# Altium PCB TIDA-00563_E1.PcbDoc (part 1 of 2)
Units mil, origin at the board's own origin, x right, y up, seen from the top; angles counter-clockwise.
Board outline 2300 x 2550 mil, 4 copper layers (Top Layer, MidLayer1 (GND), MidLayer2 (PWR), Bottom Layer), stack 79.8 mil thick; 81 components, 52 nets, 279 pads, 126 vias.
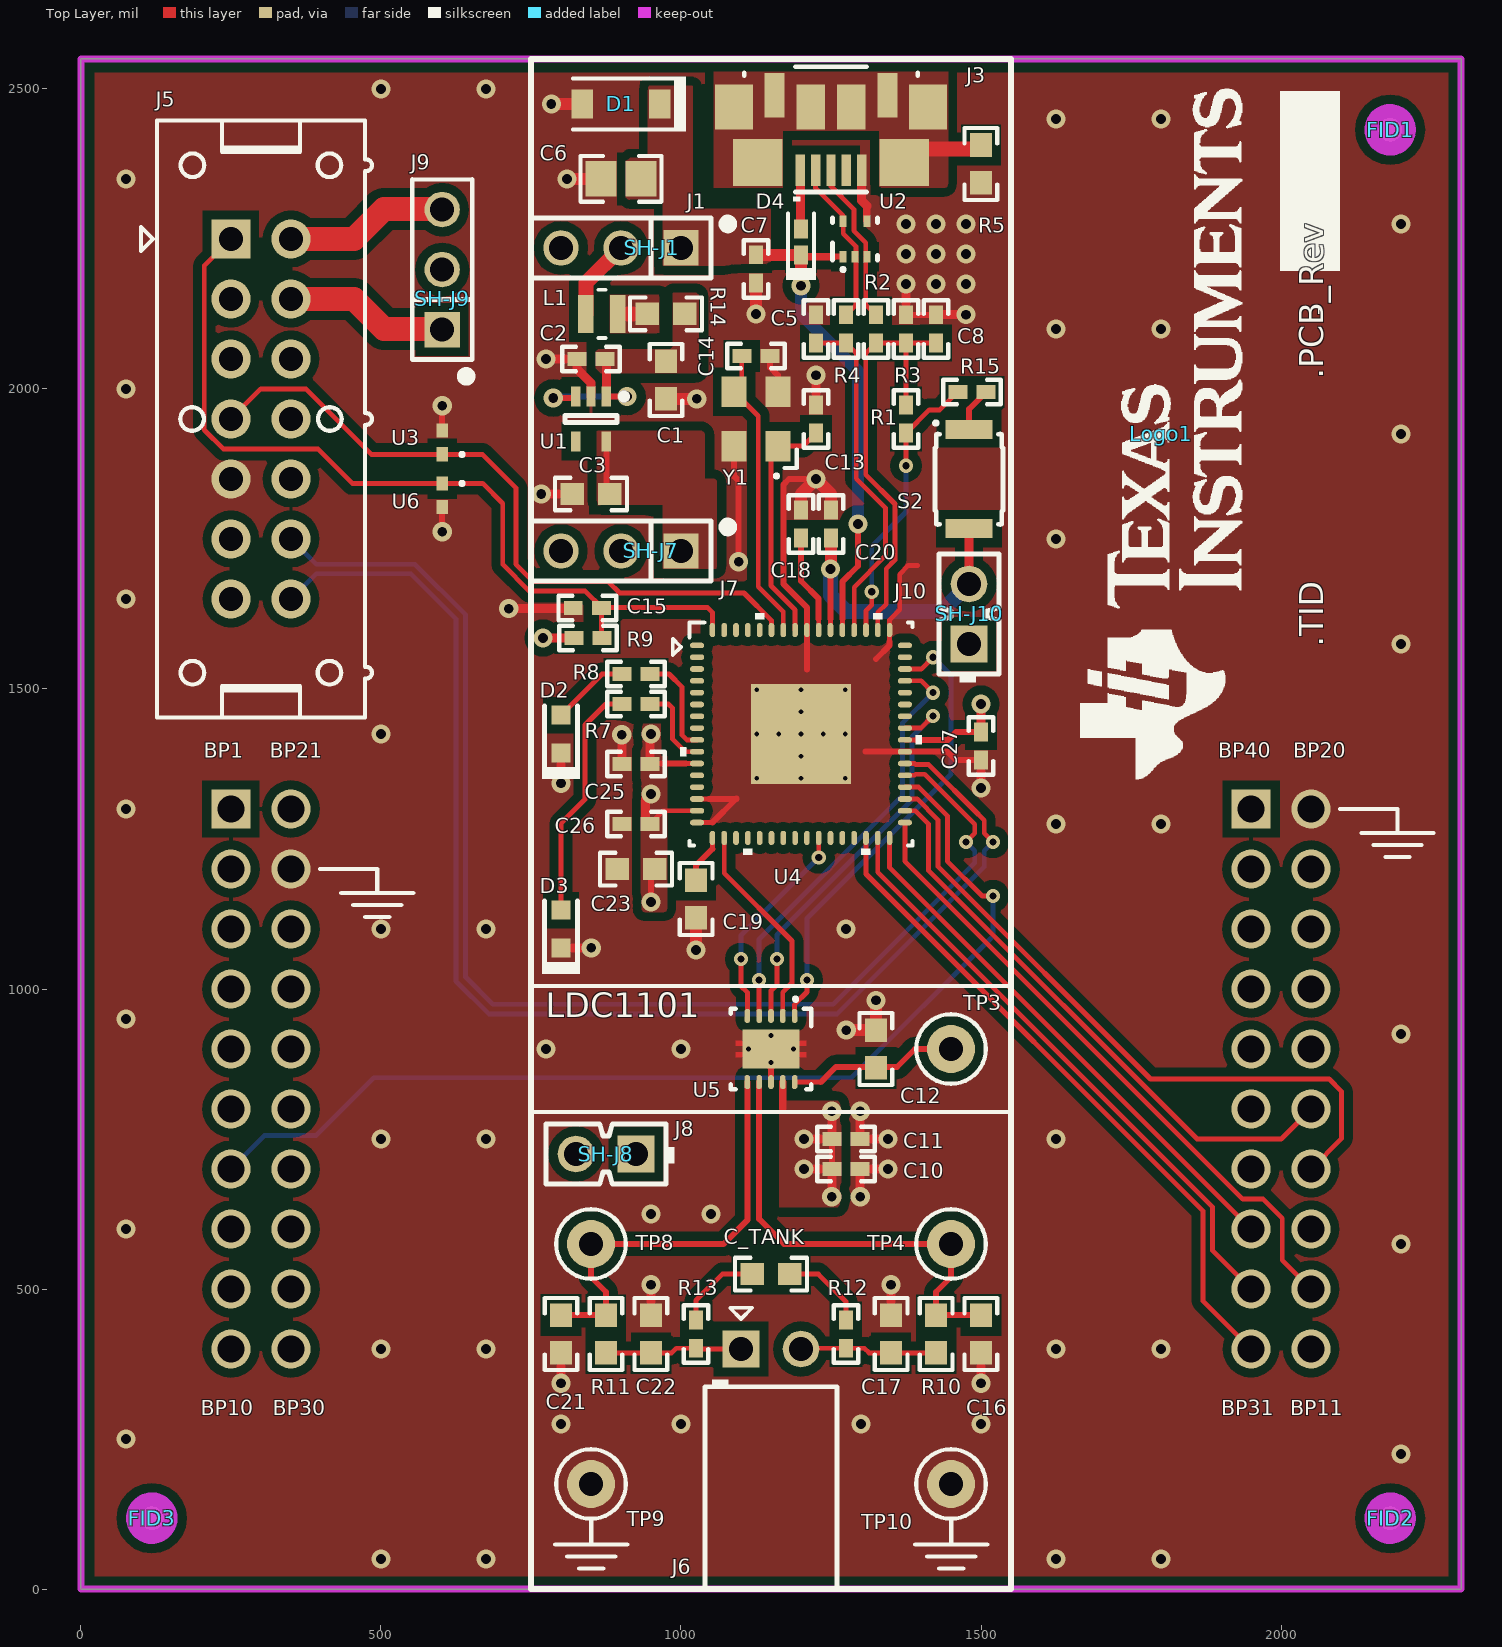
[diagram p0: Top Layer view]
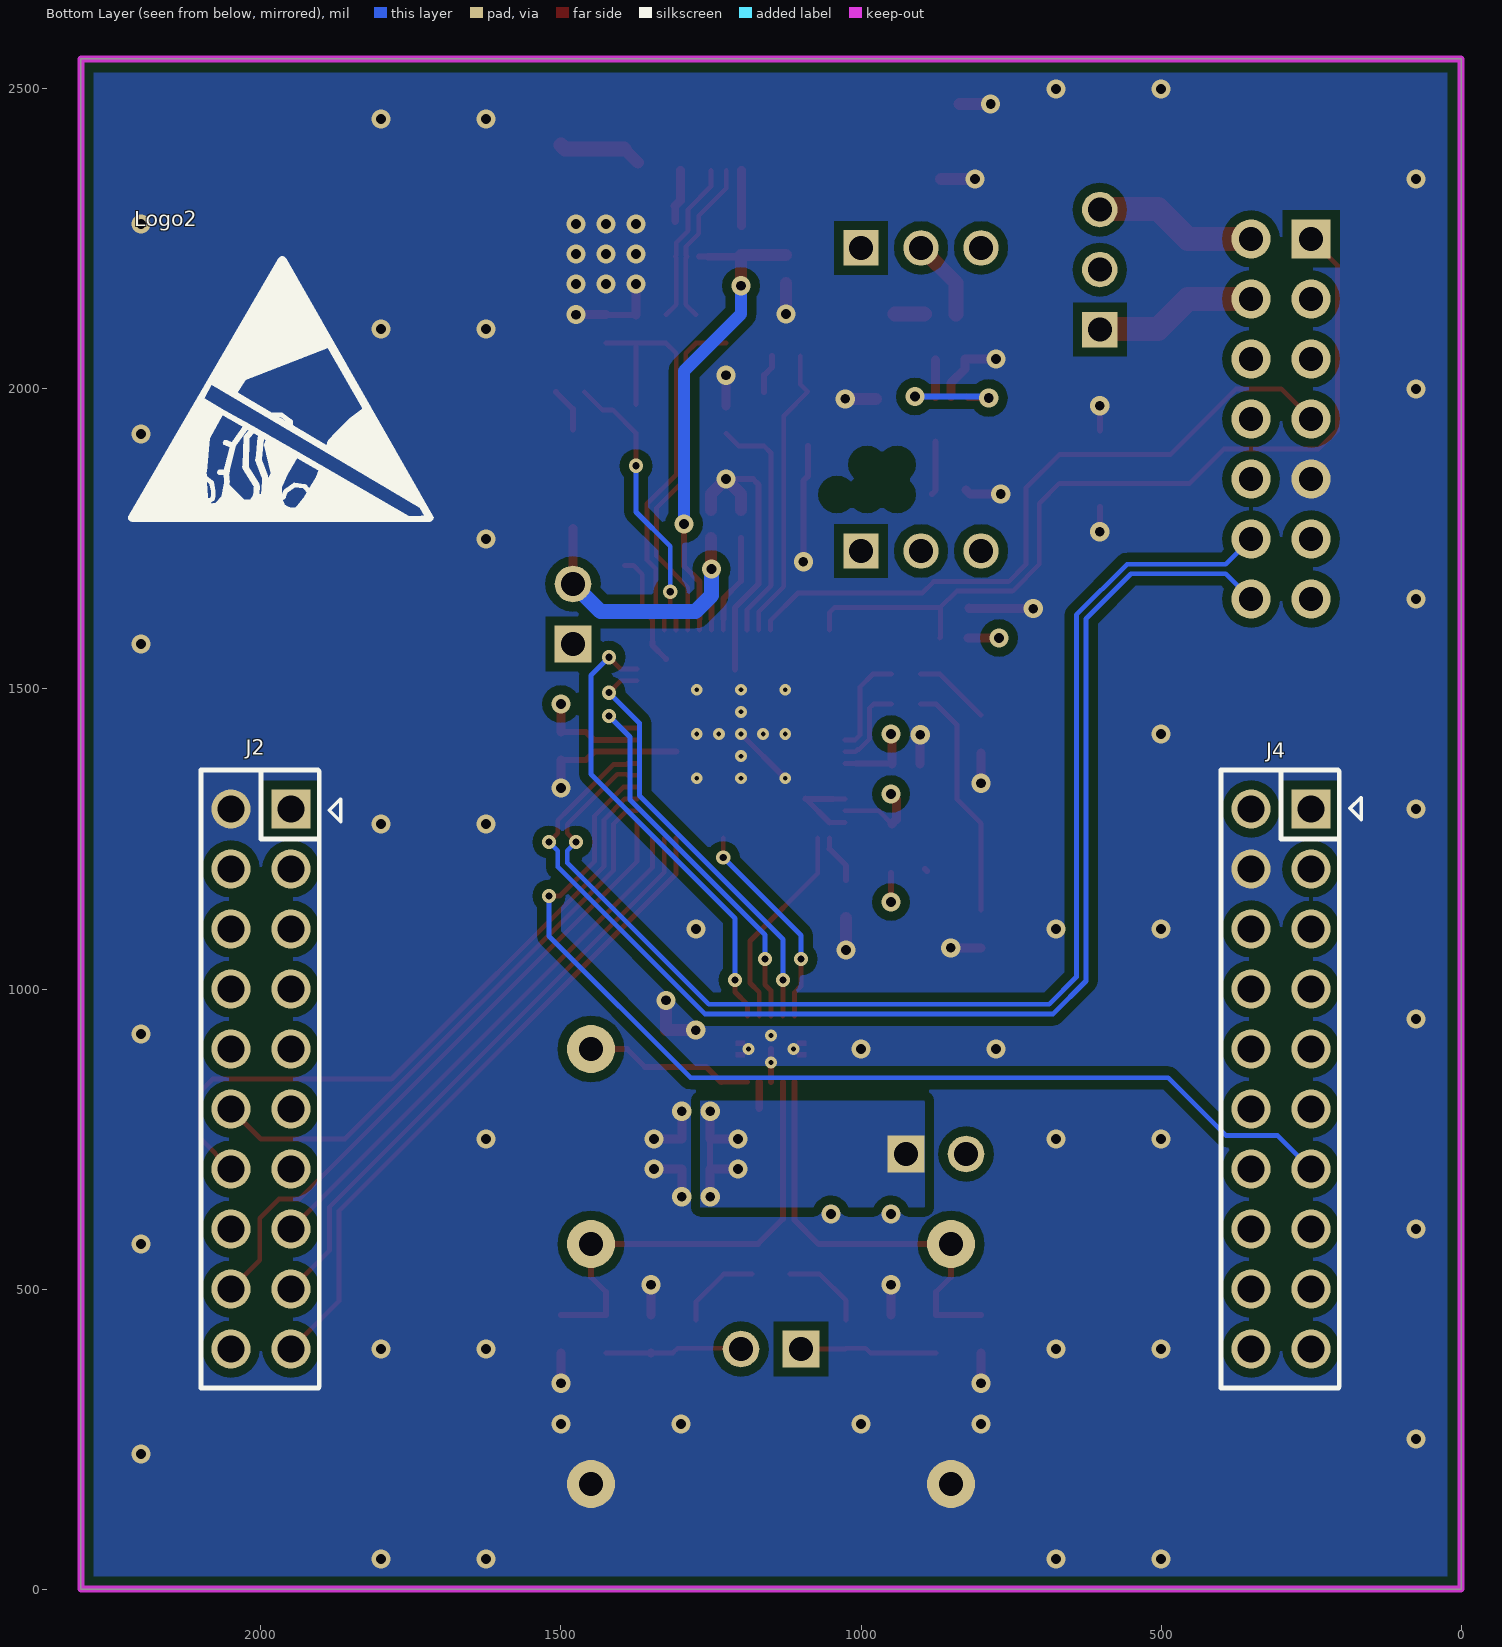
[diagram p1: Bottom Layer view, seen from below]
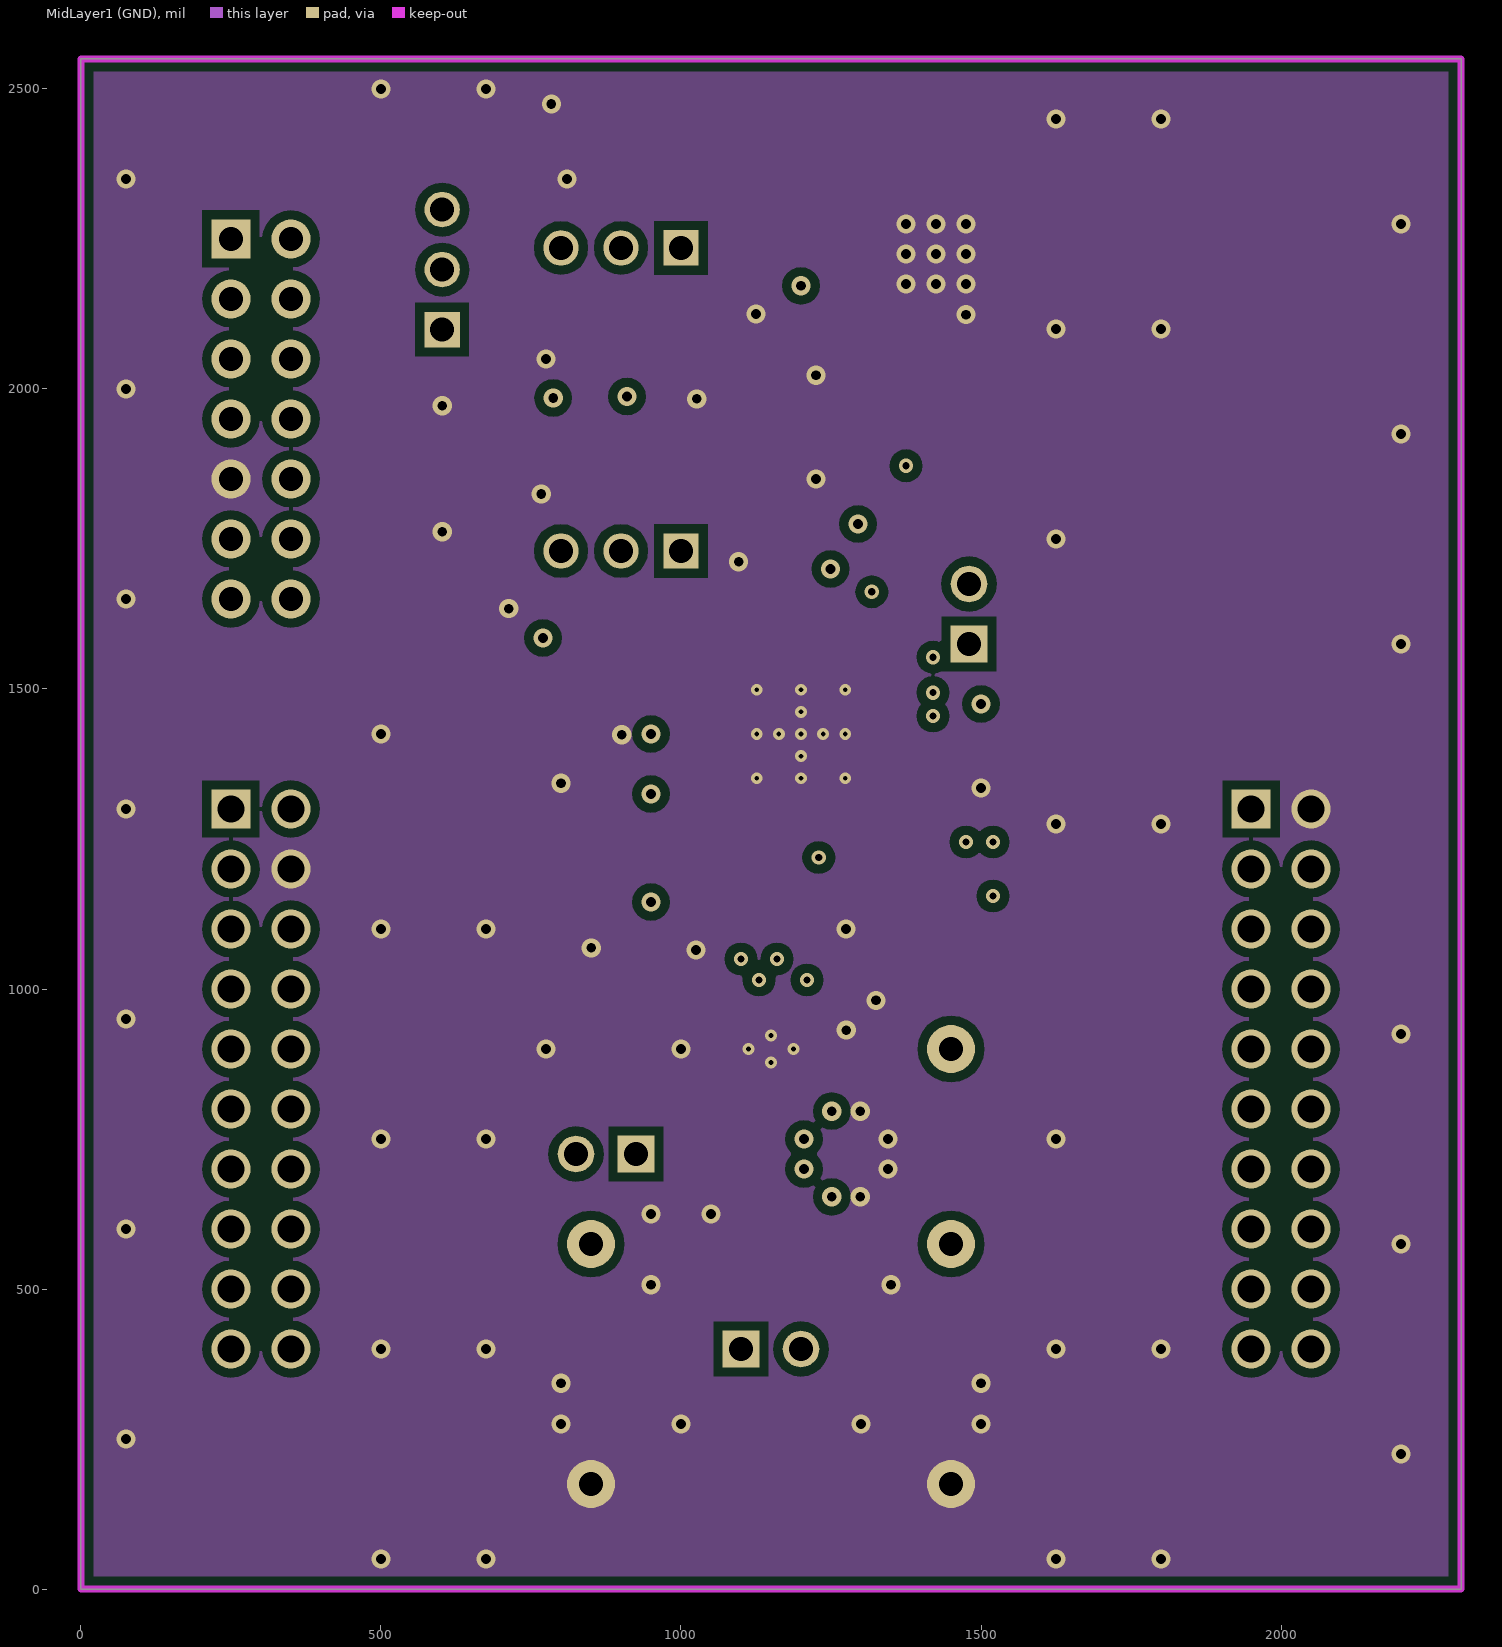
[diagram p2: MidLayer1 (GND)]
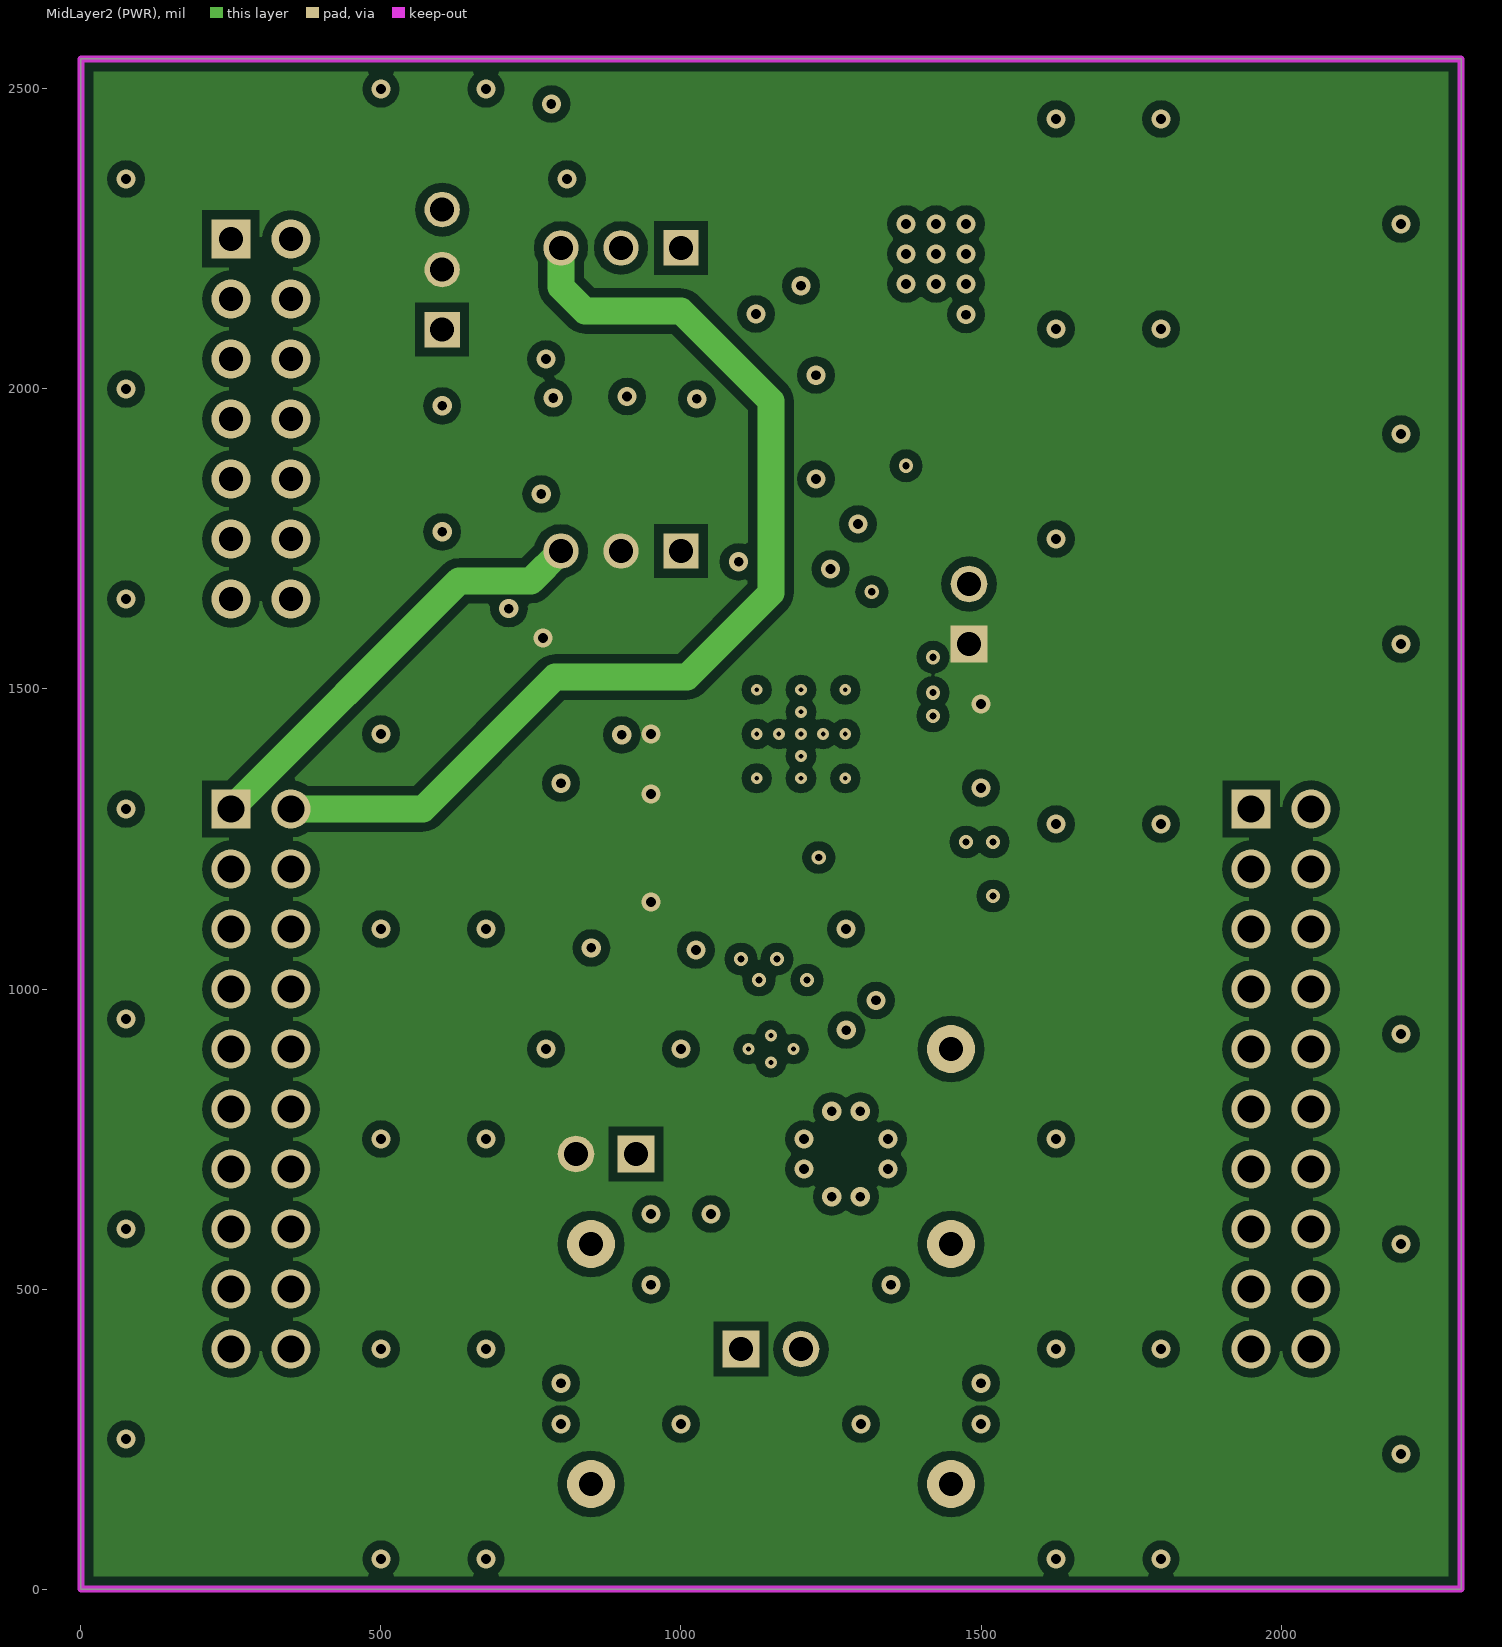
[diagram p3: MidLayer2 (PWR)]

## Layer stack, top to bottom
Top Solder: solder mask 0.4, Solder Resist, Dk 3.5
Top Layer: signal copper 1.4
Dielectric1: core 59.2, FR-4, Dk 4.8
MidLayer1 (GND): signal copper 1.4
Dielectric2: prepreg 5, Dk 4.2
MidLayer2 (PWR): signal copper 1.4
Dielectric3: core 10, Dk 4.2
Bottom Layer: signal copper 1.4
Bottom Solder: solder mask 0.4, Solder Resist, Dk 3.5

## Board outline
0,0 0,2550 2300,2550 2300,0 0,0

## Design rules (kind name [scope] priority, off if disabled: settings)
AcuteAngle [All] p1: minimum=4.50000000000000E+0001 checktracksonly=TRUE
AssemblyTestPointUsage [All] p1: valid=2
Clearance "VIA to SMD" [IsVia vs InAnyComponent] p1: gap=7.87
Clearance Clearance_BoardEdge_MountingHoles [OnCopper and InComponentClass('Mounting Holes') vs IsKeepOut] p2: gap=40
Clearance Clearance_BoardEdge_Poly [OnCopper and InPoly vs IsKeepOut] p3: gap=15
Clearance Clearance_Poly [InPolygon] p4: gap=15
Clearance [All] p5: gap=7.87
ComponentClearance ComponentClearance_MountingHoles_FiducialMarks [InComponentClass('Mounting Holes') vs InComponentClass('FiducialMark')] p1: gap=40 collisioncheckmode=3 verticalgap=10 showdistances=FALSE
ComponentClearance ComponentClearance_Shunt [InComponentClass('Header') vs InComponentClass('Shunt')] p2: gap=0 collisioncheckmode=3 verticalgap=0 showdistances=FALSE
ComponentClearance ComponentClearance_Logo [InComponentClass('Logo')] p3: gap=35 collisioncheckmode=3 verticalgap=10 showdistances=FALSE
ComponentClearance ComponentClearance_ScrewToNut [(HasFootprint('NY PMS 440 0025 PH')) vs (HasFootprint('Keystone_1902C'))] p4: gap=5 collisioncheckmode=3 verticalgap=10 showdistances=FALSE
ComponentClearance ComponentClearance_MountingHoles [InComponentClass('Mounting Holes')] p5: gap=250 collisioncheckmode=3 verticalgap=100000 showdistances=FALSE
ComponentClearance ComponentClearance_SmallPassives [HasFootprint('0201*') or HasFootprint('0402*') or HasFootprint('0508') or HasFootprint('0603*') or HasFootprint('0612') or HasFootprint('0805*') or HasFootprint('0815*') or HasFootprint('0830*') or HasFootprint('1206*') or HasFootprint('1210*') or HasFootprint('1808*') or HasFootprint('1812*') or HasFootprint('1825*') or HasFootprint('2010*') or HasFootprint('2220*') or HasFootprint('2225*') or HasFootprint('2512*') or HasFootprint('2728*') or HasFootprint('3518*') vs HasFootprint('0201*') or HasFootprint('0402*') or HasFootprint('0508') or HasFootprint('0603*') or HasFootprint('0612') or HasFootprint('0805*') or HasFootprint('0815*') or HasFootprint('0830*') or HasFootprint('1206*') or HasFootprint('1210*') or HasFootprint('1808*') or HasFootprint('1812*') or HasFootprint('1825*') or HasFootprint('2010*') or HasFootprint('2220*') or HasFootprint('2225*') or HasFootprint('2512*') or HasFootprint('2728*') or HasFootprint('3518*')] p6: gap=20 collisioncheckmode=3 verticalgap=10 showdistances=FALSE
ComponentClearance ComponentClearance_THtoSMT [IsThruComponent vs IsSMTComponent] p7: gap=50 collisioncheckmode=3 verticalgap=30 showdistances=FALSE
ComponentClearance ComponentClearance_THtoTH [IsThruComponent vs IsThruComponent] p8: gap=118.11 collisioncheckmode=3 verticalgap=30 showdistances=FALSE
ComponentClearance [All] p9: gap=30 collisioncheckmode=3 verticalgap=10 showdistances=FALSE
DiffPairsRouting DiffPair_DP_DMDiffPairsRouting [InDifferentialPair ('MSP_DP_DM_DIFF')] p1: maxlimit=8 minlimit=8 mostfreqgap=8 toplayer_minwidth=15 toplayer_maxwidth=15 toplayer_prefwidth=15 midlayer1_minwidth=15 midlayer1_maxwidth=15 midlayer1_prefwidth=15 midlayer2_minwidth=15 midlayer2_maxwidth=15 midlayer2_prefwidth=15 bottomlayer_minwidth=15 bottomlayer_maxwidth=15 bottomlayer_prefwidth=15 maxuncoupledlength=500
DiffPairsRouting DiffPair_MSP_DP_DMDiffPairsRouting [InDifferentialPair ('MSP_DP_DM_DIFF')] p2: maxlimit=8 minlimit=8 mostfreqgap=8 toplayer_minwidth=15 toplayer_maxwidth=15 toplayer_prefwidth=15 midlayer1_minwidth=15 midlayer1_maxwidth=15 midlayer1_prefwidth=15 midlayer2_minwidth=15 midlayer2_maxwidth=15 midlayer2_prefwidth=15 bottomlayer_minwidth=15 bottomlayer_maxwidth=15 bottomlayer_prefwidth=15 maxuncoupledlength=500
DiffPairsRouting [All] p3: maxlimit=8 minlimit=8 mostfreqgap=8 toplayer_minwidth=15 toplayer_maxwidth=15 toplayer_prefwidth=15 midlayer1_minwidth=15 midlayer1_maxwidth=15 midlayer1_prefwidth=15 midlayer2_minwidth=15 midlayer2_maxwidth=15 midlayer2_prefwidth=15 bottomlayer_minwidth=15 bottomlayer_maxwidth=15 bottomlayer_prefwidth=15 maxuncoupledlength=1000
FabricationTestPointUsage TestPointUsage [All] p1: valid=2 allowmultiple=FALSE
FabricationTestpoint Testpoint [All] p1: side=3 testpointundercomponent=TRUE minsize=40 maxsize=100 preferedsize=60 minholesize=0 maxholesize=40 preferedholesize=32 testpointgrid=1 allowsidetop=TRUE allowsidebottom=TRUE usegrid=TRUE gridtolerance=0.01
FanoutControl Fanout_LCC [IsLCC] p1: bgadir=Out bgaviamode=Centered fanoutstyle=Auto fanoutdirection=Alternating viagrid=1 // Fanout_LCC (Default Rule)
FanoutControl Fanout_BGA [IsBGA] p2: bgadir=Out bgaviamode=Centered fanoutstyle=Auto fanoutdirection=Alternating viagrid=1 // Fanout_BGA (Default Rule)
FanoutControl Fanout_Default [All] p4: bgadir=Out bgaviamode=Centered fanoutstyle=Auto fanoutdirection=Alternating viagrid=1 // Fanout_Default (Default Rule)
FanoutControl Fanout_Small [(CompPinCount < 5)] p5: bgadir=Out bgaviamode=Centered fanoutstyle=Auto fanoutdirection=OutThenIn viagrid=1 // Fanout_Small (Default Rule)
HoleSize [All] p1: absolutevalues=TRUE maxlimit=251 minlimit=7.87 maxpercent=80.000 minpercent=20.000
MatchedLengths DiffPair_DP_DMMatchedLengths [InDifferentialPair ('MSP_DP_DM_DIFF')] p1: tolerance=200 checknetsindiffpair=TRUE checkdiffpairvsdiffpair=TRUE checkothers=TRUE
MatchedLengths DiffPair_MSP_DP_DMMatchedLengths [InDifferentialPair ('MSP_DP_DM_DIFF')] p2: tolerance=200 checknetsindiffpair=TRUE checkdiffpairvsdiffpair=TRUE checkothers=TRUE
MinimumAnnularRing MinimumAnnularRing_ThermalPadVias [IsVia and InAnyComponent] p1: minimumring=5.91
MinimumAnnularRing [All] p2: minimumring=6
MinimumSolderMaskSliver MinimumSolderMaskSliver_Logo [InComponentClass('Logo') vs InComponentClass('Logo')] p1: minsoldermaskwidth=0.7
MinimumSolderMaskSliver [All] p2: minsoldermaskwidth=2.5
PlaneConnect [All] p1: planeconnectstyle=Direct reliefexpansion=10 reliefentries=4 reliefconductorwidth=10 reliefairgap=10
PolygonConnect [All] p1: connectstyle=Direct reliefconductorwidth=10 reliefentries=4 polygonreliefangle="90 Angle" airgapwidth=10
RoutingVias ThermalPadVias [IsVia and InAnyComponent] p1: holewidth=12 width=24 viastyle="Through Hole" minholewidth=7.87 minwidth=19.68 maxholewidth=16 maxwidth=32
RoutingVias [All] p2: holewidth=12 width=24 viastyle="Through Hole" minholewidth=10 minwidth=20 maxholewidth=16 maxwidth=32
SilkToSilkClearance SilkToSilkClearance_Pb-FreeLogo [(HasFootprint('Pb-Free_Overlay_Medium') OR HasFootprint('Pb-Free_Overlay_Small')) vs (HasFootprint('Pb-Free_Overlay_Medium') OR HasFootprint('Pb-Free_Overlay_Small'))] p1: silktosilkclearance=0
SilkToSilkClearance [All] p2: silktosilkclearance=5
SilkToSolderMaskClearance "Silk to Solder Mask Opening" [IsPad] p1: minsilkscreentomaskgap=1 clearancetoexposedcopper=TRUE
SolderMaskExpansion [All] p1: expansion=1.97
UnpouredPolygon [All] p1: allowunpoured=FALSE
Width Width_PWR [InNetClass('PWR')] p1: maxlimit=20 minlimit=10 preferedwidth=15
Width [All] p2: maxlimit=100 minlimit=8 preferedwidth=10 checkconnectedcopper=TRUE
15 further rules are at their usual default settings.

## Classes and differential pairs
component class Shunt: SH-J1 SH-J7 SH-J8 SH-J9 SH-J10
component class Header: J8 J10
component class Logo: Logo1
component class TIDA-00563_E1_Hardware: FID1 FID2 FID3 Logo1 Logo2 ZZ1 ZZ2 ZZ3 ZZ4
component class FiducialMark: FID1 FID2 FID3
component class AssemblyNote: ZZ1 ZZ2 ZZ3 ZZ4
component class TIDA-00563_E1_LDC1101_BoosterPack: C1 C2 C3 C5 C6 C7 C8 C10 C11 C12 C13 C14 C15 C16 C17 C18 C19 C20 C21 C22 C23 C25 C26 C27 C_TANK D1 D2 D3 D4 J1 J2 J3 J4 J5 J6 J7 J8 J9 J10 L1 R1 R2 R3 R4 R5 R7 R8 R9 R10 R11 R12 R13 R14 R15 S2 SH-J1 SH-J7 SH-J8 SH-J9 SH-J10 TP3 TP4 TP8 TP9 TP10 U1 U2 U3 U4 U5 U6 Y1

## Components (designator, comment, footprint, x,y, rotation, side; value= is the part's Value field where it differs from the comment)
C1 "C0603C225K8PACTU" 0603 975,2015 r270 top
C2 "C1005X7R1H104K050BB" 0402 850,2050 r180 top
C3 "C0603C225K8PACTU" 0603 850,1825 r180 top
C5 "500R07S100JV4T" 0402 1225,2100 r90 top
C6 "GRM21BR71C475KA73L" 0805 900,2350 r180 top
C7 "C1005X7R1H104K050BB" 0402 1125,2200 r270 top
C8 "500R07S100JV4T" 0402 1425,2100 r90 top
C10 "GRM155R61A105KE15D" 0402 1275,700 r0 top
C11 "C1005X7R1H104K050BB" 0402 1275,750 r0 top
C12 "GRM188R71C153KA01D" 0603 1325,900 r90 top
C13 "GRM1555C1H180JA01D" 0402 1225,1950 r90 top
C14 "GRM1555C1H180JA01D" 0402 1125,2055 r0 top
C15 "GRM155R70J222KA01D" 0402 844,1635 r180 top
C16 "GRM1885C2A180JA01D" 0603 1500,425 r90 top
C17 "GRM1885C2A180JA01D" 0603 1350,425 r270 top
C18 "0402YC132KAT2A" 0402 1200,1775 r90 top
C19 "C0603C474K8RACTU" 0603 1025,1150 r270 top
C20 "0402YC132KAT2A" 0402 1250,1775 r90 top
C21 "GRM1885C2A180JA01D" 0603 800,425 r270 top
C22 "GRM1885C2A180JA01D" 0603 950,425 r90 top
C23 "C1608X5R1A106M" 0603 925,1200 r180 top
C25 "C1005X7R1H104K050BB" 0402 925,1375 r180 top
C26 "C1005X7R1H104K050BB" 0402 925,1275 r180 top
C27 "C1005X7R1H104K050BB" 0402 1500,1405 r270 top
C_TANK "C1608C0G1H331F080AA" 0603 1150,525 r180 top
D1 "MMSZ5232B-7-F" SOD-123 900,2475 r180 top
D2 "150060GS75000" WL-SMCW_GREEN 800,1425 r90 top
D3 "150060RS75000" WL-SMCW_RED 800,1100 r90 top
D4 "SBR0220T5-7-F" SOD-523 1200,2245 r90 top
FID1 "Fiducial" Fiducial10-20 2181.89,2431.89 r0 top
FID2 "Fiducial" Fiducial10-20 2181.89,118.11 r0 top
FID3 "Fiducial" Fiducial10-20 118.11,118.11 r0 top
J1 "PEC03SAAN" CONN_PEC03SAAN 900,2235 r180 top
J2 "SSW-110-23-F-D" CONN_SSW-110-23-F-D 2000,850 r90 bottom locked
J3 "ZX62R-B-5P" Hirose_ZX62R-B-5P 1250,2470 r90 top
J4 "SSW-110-23-F-D" CONN_SSW-110-23-F-D 300,850 r90 bottom locked
J5 "SBH11-PBPC-D07-ST-BK" CONN_SBH11-PBPC-D07-ST-BK 300,1950 r270 top
J6 "PPTC021LGBN-RC" Sullins_xPxC021LGBN 1150,400 r0 top
J7 "PEC03SAAN" CONN_PEC03SAAN 900,1730 r180 top
J8 "TSW-102-07-T-S" Samtec_TSW-102-07-T-S 875,725 r180 top
J9 "PEC03SAAN" CONN_PEC03SAAN 602,2199 r90 top
J10 "TSW-102-07-T-S" Samtec_TSW-102-07-T-S 1480,1625 r90 top
L1 "VLS201610ET-100M" VLS201610ET 868,2125 r0 top
Logo1 "Texas Instruments" TI_Stacked_Overlay_Medium_Vertical 1800,1925 r0 top
Logo2 "ESD Susceptible" ESD_Overlay_Large 1965,2000 r180 bottom
R1 "ERJ-2RKF1401X" 0402 1375,1950 r270 top
R2 "CRCW040227R0JNED" 0402 1325,2100 r270 top
R3 "CRCW040233K0JNED" 0402 1375,2100 r270 top
R4 "CRCW040227R0JNED" 0402 1275,2100 r270 top
R5 "CRCW060333R0JNEA" 0603 1500,2375 r90 top
R7 "CRCW04021K00JNED" 0402 925,1475 r180 top
R8 "CRCW04021K00JNED" 0402 925,1525 r180 top
R9 "CRCW040233K0JNED" 0402 845,1585 r0 top
R10 "ERJ-3GEY0R00V" 0603 1425,425 r270 top
R11 "ERJ-3GEY0R00V" 0603 875,425 r270 top
R12 "CRCW04020000Z0ED" 0402 1275,425 r270 top
R13 "CRCW04020000Z0ED" 0402 1025,425 r90 top
R14 "RC0603FR-074R99L" 0603 975,2125 r0 top
R15 "ERJ-2RKF1000X" 0402 1485,1995 r0 top
S2 "SKRKAEE010" SW_SKRKAEE010 1480,1850 r270 top
SH-J1 "969102-0000-DA" SNT-100-BK-G 951,2235 r180 top
SH-J7 "969102-0000-DA" SNT-100-BK-G 950,1730 r0 top
SH-J8 "969102-0000-DA" SNT-100-BK-G 875,725 r180 top
SH-J9 "969102-0000-DA" SNT-100-BK-G 602,2150 r90 top
SH-J10 "969102-0000-DA" SNT-100-BK-G 1480,1625 r90 top
TP3 "5000" Keystone5000 1450,900 r0 top
TP4 "5002" Keystone5002 1450,575 r0 top
TP8 "5002" Keystone5002 850,575 r0 top
TP9 "5001" Keystone5001 850,175 r0 top
TP10 "5001" Keystone5001 1450,175 r90 top
U1 "LP5951MG-3.3/NOPB" MAA05A_N 850,1950 r270 top
U2 "TPD2E001DRLR" DRL0005A 1290,2250 r90 top
U3 "TPD1E10B06DPYR" DPY0002A 602,1911 r90 top
U4 "MSP430F5528IRGC" RGC0064B 1200,1425 r0 top
U5 "LDC1101DRC" DRC0010J 1150,900 r270 top
U6 "TPD1E10B06DPYR" DPY0002A 602,1823 r270 top
Y1 "ABM8-24.000MHZ-B2-T" XTAL_ABM8 1125,1950 r180 top
ZZ1 "This Assembly Note is for PCB labels only" AssemblyNoteLabel 185,3938 r0 top
ZZ2 "This Assembly Note will show in the PcbDoc and associated outputs" AssemblyNote 185,3829.11 r0 top
ZZ3 "This Assembly Note will show in the PcbDoc and associated outputs" AssemblyNote 185,3740.56 r0 top
ZZ4 "This Assembly Note will show in the PcbDoc and associated outputs" AssemblyNote 185,3652 r0 top

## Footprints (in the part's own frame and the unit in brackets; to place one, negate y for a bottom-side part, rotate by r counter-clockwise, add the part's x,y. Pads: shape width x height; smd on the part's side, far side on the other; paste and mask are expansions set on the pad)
0402 [mm] "0402 from SM-752 data"
  rect 0.8x0.6 smd: 1(-0.6,0) 2(0.6,0)
  silkscreen extent -1.22,-0.52 1.22,0.52, body extent -0.55,-0.3 0.55,0.3, height 0.6
0603 [mm] "0603 from SM-752 data"
  rect 1x0.95 smd: 1(-0.8,0) 2(0.8,0)
  silkscreen extent -1.52,-0.69 1.52,0.69, body extent -0.87,-0.47 0.87,0.47, height 1
0805 [mm] "0805 from SM-752 data"
  rect 1.3x1.5 smd: 1(-0.85,0) 2(0.85,0)
  silkscreen extent -1.72,-0.97 1.72,0.97, body extent -1.1,-0.72 1.1,0.72, height 1.45
AssemblyNote [mil] "Assembly Note"
AssemblyNoteLabel [mil] "Assembly Note for PCB Labels"
CONN_PEC03SAAN [mm] "SULLINS"
  rect 1.5x1.5 hole 1.016: 1(-2.54,0)
  round 1.5 hole 1.016: 2(0,0) 3(2.54,0)
  silkscreen extent -4.72,-1.27 3.81,1.27, body extent -3.84,-1.3 3.84,1.3, height 8.38
CONN_SBH11-PBPC-D07-ST-BK [mm] "Sullins recommended land pattern"
  rect 1.65x1.65 hole 1.016 mask+0.05: 1(-7.62,-1.27)
  round 1.65 hole 1.016 mask+0.05: 2(-7.62,1.27) 3(-5.08,-1.27) 4(-5.08,1.27) 5(-2.54,-1.27) 6(-2.54,1.27) 7(0,-1.27) 8(0,1.27) 9(2.54,-1.27) 10(2.54,1.27) 11(5.08,-1.27) 12(5.08,1.27) 13(7.62,-1.27) 14(7.62,1.27)
  silkscreen extent -12.64,-5.08 12.64,4.7, body extent -12.64,-4.4 12.64,4.7, height 9.12
CONN_SSW-110-23-F-D [mm] "SAMTEC"
  rect 1.65x1.65 hole 1.15: 1(11.43,-1.27)
  round 1.65 hole 1.15: 2(11.43,1.27) 3(8.89,-1.27) 4(8.89,1.27) 5(6.35,-1.27) 6(6.35,1.27) 7(3.81,-1.27) 8(3.81,1.27) 9(1.27,-1.27) 10(1.27,1.27) 11(-1.27,-1.27) 12(-1.27,1.27) 13(-3.81,-1.27) 14(-3.81,1.27) 15(-6.35,-1.27) 16(-6.35,1.27) 17(-8.89,-1.27) 18(-8.89,1.27) 19(-11.43,-1.27) 20(-11.43,1.27)
  silkscreen extent -13.08,-2.46 13.08,2.54, body extent -13,-2.51 13,2.54, height 8.59
DPY0002A [mm] "R-PX2SON-N2"
  rect 0.6x0.5 smd: 1(-0.5,0) 2(0.5,0)
  body extent -0.55,-0.35 0.55,0.35, height 0.4
DRC0010J [mm] "SON, 10-Leads, Body 3x3mm, Pitch 0.5mm, Thermal Pad 2.4x1.65mm, TI Recommended"
  oval 0.6x0.24 smd: 1(-1.4,1) 2(-1.4,0.5) 3(-1.4,0) 4(-1.4,-0.5) 6(1.4,-1) 7(1.4,-0.5) 8(1.4,0) 9(1.4,0.5) 10(1.4,1)
  oval 0.6x0.24 smd mask+0.05: 5(-1.4,-1)
  rect 1.65x2.4 smd paste-0.825: 11(0,0)
  Top Layer region: 0.135,1.1 0.365,1.1 0.365,1.5 0.135,1.5
  Top Layer region: -0.135,1.5 -0.365,1.5 -0.365,1.1 -0.135,1.1
  Top Layer region: -0.135,-1.1 -0.365,-1.1 -0.365,-1.5 -0.135,-1.5
  Top Layer region: 0.135,-1.5 0.365,-1.5 0.365,-1.1 0.135,-1.1
  silkscreen extent -1.7,-1.7 1.7,1.7, body extent -1.55,-1.55 1.55,1.55, height 1.01
DRL0005A [mm] "SOTFL, 5-Flat Leads, Body 1.2x1.6x0.6mm, Pitch 0.5mm, TI recommended"
  rect 0.5x0.3 smd: 1(-0.75,0.5) 2(-0.75,0) 3(-0.75,-0.5) 4(0.75,-0.5) 5(0.75,0.5)
  silkscreen extent -0.9,-0.95 0.9,0.95, body extent -0.85,-0.85 0.85,0.85, height 0.62
ESD_Overlay_Large [mil]
  silkscreen extent -254,-219 250,219
Fiducial10-20 [mm]
  round 1 smd mask+0.5: 1(0,0)
  Top Layer keep-out circle w1.178: c0,0 r0.5
Hirose_ZX62R-B-5P [mm] "Hirose"
  rect 1.35x0.4 smd: 1(-2.68,1.3) 2(-2.68,0.65) 3(-2.68,0) 4(-2.68,-0.65) 5(-2.68,-1.3)
  rect 2x2.1 smd: 6(-2.35,-3.1) 7(-2.35,3.1)
  rect 1.9x1.6 smd: 8(0,-4.1) 13(0,4.1)
  rect 1.88x0.85 smd: 9(0.495,-2.4) 12(0.495,2.4)
  rect 1.9x1.2 smd: 10(0,-0.85) 11(0,0.85)
  silkscreen extent -4,-3.67 1.7,3.67, body extent -2.57,-3.48 2.11,3.45, height 2.65
Keystone5000 [mil] "For Keystone 500x miniature loop terminals"
  round 80 hole 40: 1(0,0)
  silkscreen extent -58,-58 58,58, body extent -49,-49 49,49, height 182
Keystone5001 [mil] "For Keystone 500x miniature loop terminals"
  round 80 hole 40: 1(0,0)
  silkscreen extent -58,-58 58,58, body extent -49,-49 49,49, height 182
Keystone5002 [mil] "For Keystone 500x miniature loop terminals"
  round 80 hole 40: 1(0,0)
  silkscreen extent -58,-58 58,58, body extent -49,-49 49,49, height 182
MAA05A_N [mm] "SOT353, 5-Leads, Body 2x1.3mm, Pitch 0.65mm, Lead Span 2.1mm, IPC Medium Density"
  rect 0.85x0.4 smd: 1(-0.95,0.65) 2(-0.95,0) 3(-0.95,-0.65) 4(0.95,-0.65) 5(0.95,0.65)
  silkscreen extent -1.07,-1.1 0.15,1.53, body extent -0.7,-1.1 0.7,1.1, height 1.1
RGC0064B [mm]
  oval 0.6x0.24 smd mask+0.07: 1(-4.4,3.75) 2(-4.4,3.25) 3(-4.4,2.75) 4(-4.4,2.25) 5(-4.4,1.75) 6(-4.4,1.25) 7(-4.4,0.75) 8(-4.4,0.25) 9(-4.4,-0.25) 10(-4.4,-0.75) 11(-4.4,-1.25) 12(-4.4,-1.75) 13(-4.4,-2.25) 14(-4.4,-2.75) 15(-4.4,-3.25) 16(-4.4,-3.75) 33(4.4,-3.75) 34(4.4,-3.25) 35(4.4,-2.75) 36(4.4,-2.25) 37(4.4,-1.75) 38(4.4,-1.25) 39(4.4,-0.75) 40(4.4,-0.25) 41(4.4,0.25) 42(4.4,0.75) 43(4.4,1.25) 44(4.4,1.75) 45(4.4,2.25) 46(4.4,2.75) 47(4.4,3.25) 48(4.4,3.75)
  oval 0.24x0.6 smd mask+0.07: 17(-3.751,-4.4) 18(-3.251,-4.4) 19(-2.751,-4.4) 20(-2.251,-4.4) 21(-1.75,-4.4) 22(-1.25,-4.4) 23(-0.75,-4.4) 24(-0.25,-4.4) 25(0.25,-4.4) 26(0.75,-4.4) 27(1.25,-4.4) 28(1.75,-4.4) 29(2.251,-4.4) 30(2.751,-4.4) 31(3.251,-4.4) 32(3.751,-4.4) 49(3.751,4.4) 50(3.251,4.4) 51(2.751,4.4) 52(2.251,4.4) 53(1.75,4.4) 54(1.25,4.4) 55(0.75,4.4) 56(0.25,4.4) 57(-0.25,4.4) 58(-0.75,4.4) 59(-1.25,4.4) 60(-1.75,4.4) 61(-2.251,4.4) 62(-2.751,4.4) 63(-3.251,4.4) 64(-3.751,4.4)
  rect 4.25x4.25 smd paste-2.112: 65(0,0)
  silkscreen extent -5.1,-5.1 5.1,5.1, body extent -4.57,-4.57 4.57,4.57, height 1.01
Samtec_TSW-102-07-T-S [mm] "Header, 2.54 mm, 2x1, Tin, TH"
  rect 1.55x1.55 hole 1.02: 1(-1.27,0)
  round 1.55 hole 1.02: 2(1.27,0)
  silkscreen extent -2.9,-1.27 2.54,1.27, body extent -2.54,-1.27 2.54,1.27, height 8.38
SNT-100-BK-G [mil] "Samtec STEP model"
  round 1 on Mech3: 0(0,0)
  body extent -100,-50 100,50, height 344
SOD-123 [mm] "On Semi recommended land pattern"
  rect 0.915x1.22 smd: 1(-1.637,0) 2(1.637,0)
  silkscreen extent -2.74,-1.17 2.03,1.17, body extent -1.93,-0.9 1.93,0.9, height 1.35
SOD-523 [mm] "NXP Semiconductor recommended land pattern, nominal STEP model"
  rect 0.8x0.6 smd paste-0.05: 1(-0.55,0) 2(0.55,0)
  silkscreen extent -1.6,-0.64 1.2,0.63, body extent -0.8,-0.4 0.8,0.4, height 0.72
Sullins_xPxC021LGBN [mm] "Receptacle, 2.54 mm, 2x1, R/A, SMT"
  rect 1.55x1.55 hole 1.02: 1(-1.27,0)
  round 1.55 hole 1.02: 2(1.27,0)
  silkscreen extent -2.79,-10 2.79,-1.3, body extent -2.79,-10.25 2.79,0.2, height 2.74
SW_SKRKAEE010 [mm] "Alps recommended land pattern"
  rect 0.8x2 smd: 1(-2.1,0) 2(2.1,0)
  silkscreen extent -1.9,-1.44 1.92,1.44, body extent -2.4,-1.45 2.4,1.45, height 1.96
TI_Stacked_Overlay_Medium_Vertical [mil]
  silkscreen extent -135,-576 135,576
VLS201610ET [mm] "TDK"
  rect 0.65x1.6 smd: 1(-0.675,0) 2(0.675,0)
  silkscreen extent -0.15,-1.02 0.15,1.02, body extent -1.05,-0.85 1.05,0.85, height 0.95
WL-SMCW_GREEN [mm] "WURTH"
  rect 0.8x0.8 smd: 1(-0.8,0) 2(0.8,0)
  silkscreen extent -1.9,-0.8 1.2,0.8, body extent -0.85,-0.45 0.85,0.45, height 0.8
WL-SMCW_RED [mm] "WURTH"
  rect 0.8x0.8 smd: 1(-0.8,0) 2(0.8,0)
  silkscreen extent -1.9,-0.8 1.2,0.8, body extent -0.85,-0.45 0.85,0.45, height 0.8
XTAL_ABM8 [mm] "Abracon recommended land pattern"
  rect 1.05x1.3 smd: 1(-0.925,1.15) 2(-0.925,-1.15) 3(0.925,-1.15) 4(0.925,1.15)
  silkscreen extent -1.73,1.3 -1.2,2.07, body extent -1.35,-1.7 1.35,1.7, height 0.8

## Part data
C1 C3: "CAP, CERM, 2.2 µF, 10 V, +/- 10%, X5R, 0603"
C2 C7 C11 C25 C26 C27: "CAP, CERM, 0.1 µF, 50 V, +/- 10%, X7R, 0402"
C5 C8: "CAP, CERM, 10 pF, 50 V, +/- 5%, C0G/NP0, 0402"
C6: "CAP, CERM, 4.7 µF, 16 V, +/- 10%, X7R, 0805"
C10: "CAP, CERM, 1 µF, 10 V, +/- 10%, X5R, 0402"
C12: "CAP, CERM, 0.015 µF, 16 V, +/- 10%, X7R, 0603"
C13 C14: "CAP, CERM, 18 pF, 50 V, +/- 5%, C0G/NP0, 0402"
C15: "CAP, CERM, 2200 pF, 6.3 V, +/- 10%, X7R, 0402"
C16 C17 C21 C22: "CAP, CERM, 18 pF, 100 V, +/- 5%, C0G/NP0, 0603"
C18 C20: "CAP, CERM, 1300 pF, 16 V, +/- 10%, X7R, 0402"
C19: "CAP, CERM, 0.47 µF, 10 V, +/- 10%, X7R, 0603"
C23: "CAP, CERM, 10 µF, 10 V, +/- 20%, X5R, 0603"
C_TANK: "CAP, CERM, 330 pF, 50 V, +/- 1%, C0G/NP0, 0603"
D1: "Diode, Zener, 5.6 V, 500 mW, SOD-123"
D2: "LED, Green, SMD"
D3: "LED, Red, SMD"
D4: "Diode, Schottky, 20 V, 0.2 A, SOD-523"
FID1 FID2 FID3: "Fiducial mark.  There is nothing to buy or mount."
J1 J7 J9: "Header, 100mil, 3x1, Tin plated, TH"
J2 J4: "Connector, Receptacle, 100mil, 10x2, Gold plated, TH"
J3: "Connector, Receptacle, Micro-USB Type B, SMT"
J5: "Header (shrouded), 100 mil, 7x2, Gold plated, TH"
J6: "Receptacle, 2.54 mm, 2x1, Tin, R/A, SMT"
J8 J10: "Header, 2.54 mm, 2x1, Tin, TH"
L1: "Inductor, Shielded, Ferrite, 10 µH, 0.4 A, 1.38 ohm, SMD"
Logo1: library part TI_Logo, "Texas Instrument Corporate Signature"
Logo2: library part ESD_Susceptible, "ESD Susceptible Symbol"
R1: "RES, 1.40 k, 1%, 0.1 W, 0402"
R2 R4: "RES, 27, 5%, 0.063 W, 0402"
R3 R9: "RES, 33 k, 5%, 0.063 W, 0402"
R5: "RES, 33, 5%, 0.1 W, 0603"
R7 R8: "RES, 1.0 k, 5%, 0.063 W, 0402"
R10 R11: "RES, 0, 5%, 0.1 W, 0603"
R12 R13: "RES, 0, 5%, 0.063 W, 0402"
R14: "RES, 4.99, 1%, 0.1 W, 0603"
R15: "RES, 100, 1%, 0.1 W, 0402"
S2: "Switch, Push Button, SMD"
SH-J1 SH-J7 SH-J8 SH-J9 SH-J10: "Shunt, 100mil, Gold plated, Black"
TP3: "Test Point, Miniature, Red, TH"
TP4 TP8: "Test Point, Miniature, White, TH"
TP9 TP10: "Test Point, Miniature, Black, TH"
U1: "Micropower, 150mA Low-Dropout CMOS Voltage Regulator, 5-pin SC-70, Pb-Free"
U2: "Low-Capacitance + / - 15 kV ESD-Protection Array for High-Speed Data Interfaces, 2 Channels, -40 to +85 degC, 5-pin SOT (DRL), Green (RoHS & no Sb/Br)"
U3 U6: "ESD in 0402 Package with 10 pF Capacitance and 6 V Breakdown, 1 Channel, -40 to +125 degC, 2-pin X2SON (DPY), Green (RoHS & no Sb/Br)"
U4: "Mixed Signal MicroController, RGC0064B"
U5: "1.8V High Resolution Inductance to Digital Converter, DRC0010J"
Y1: "Crystal, 24.000MHz, 18pF, SMD"
ZZ1: library part AssemblyNoteLabel
ZZ2 ZZ3 ZZ4: library part AssemblyNote

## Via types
v1: diameter 32, hole 16, Top Layer to Bottom Layer, tented both sides, 96 vias
v2: diameter 19.68, hole 7.87, Top Layer to Bottom Layer, 17 vias
v3: diameter 24, hole 12, Top Layer to Bottom Layer, tented both sides, 13 vias

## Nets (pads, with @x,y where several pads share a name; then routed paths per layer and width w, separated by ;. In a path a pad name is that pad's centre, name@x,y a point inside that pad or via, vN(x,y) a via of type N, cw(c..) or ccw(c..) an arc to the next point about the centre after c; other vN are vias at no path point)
+3.3V: C23.1 C25.1 C26.1 C27.1 J7.2 J8.2 J9.2 J10.1 R9.1 U4.11 U4.15 U4.40 | length 552.3
  Top Layer w8: C26.1@948.62,1275 970.67,1297.04 U4.15@1026.78,1297.04 ; 1008,1375.78 U4.11@1026.78,1375.78 ; U4.40@1373.23,1415.15 1392.01,1415.15
  Top Layer w10: v1@941,1316 v1(950,1325) ; C25.1@948.63,1375 949.41,1375.78 1008,1375.78 ; v1(950,1145) C23.1@950,1193.5 ; 1390.92,1415.15 1445.15,1415.15 1458.62,1428.62 C27.1@1500,1428.62
  Top Layer w15: v1(770,1585) R9.1@821.38,1585 ; v1@941,1316 941,1282.62 C26.1@948.62,1275 ; C25.1@948.63,1375 v1@948.63,1425 ; C27.1@1500,1428.62 v1(1500,1475)
  other v1: 950,1425
+3.3V_LDO: C3.1 J7.1 U1.5 | length 90
  Top Layer w10: U1.5@875.59,1912.6 875.59,1830.9 C3.1@881.5,1825
+3.3V_LP: J4.1 J7.3 | length 728.1
  MidLayer2 (PWR) w45: J4.1@250,1300 630.37,1680.37 750.37,1680.37 J7.3@800,1730
+5V_LP: J1.3 J4.2 | length 1762.8
  MidLayer2 (PWR) w45: J4.2@350,1300 570,1300 790,1520 1010,1520 1150,1660 1150,1980 1000,2130 840,2130 800,2170 J1.3@800,2235
CLK_MSP: C13.1 U4.57 Y1.1 | length 400.4
  Top Layer w8: U4.57@1190.16,1598.23 1190,1598.38 1190,1632 1150,1672 1150,1893.3 Y1.1@1161.42,1904.72 1203.35,1904.72 C13.1@1225,1926.37
COILA: C17.2 J6.2 R10.2 R12.2 | length 228.8
  Top Layer w8: J6.2@1201.38,401.38 R12.2@1275,401.38 1305.62,401.38 1313.5,393.5 C17.2@1350,393.5 R10.2@1425,393.5
  Top Layer w15: J6.2@1200,400 J6.2@1201.38,401.38
COILB: C22.1 J6.1 R11.2 R13.1 | length 228.8
  Top Layer w8: R11.2@875,393.5 C22.1@950,393.5 984.5,393.5 992.38,401.38 R13.1@1025,401.38 1026.38,400 J6.1@1100,400
CS_BP: J2.18 U4.33 | length 1077.5
  Top Layer w8: U4.33@1373.23,1277.36 1373.23,1212.9 1936.14,650 1970,650 2002,618 2002,548.01 J2.18@2050,500
DMROUTE: J3.2 R4.1 U2.2 U2.5 | length 277.3
  Top Layer w8: J3.2@1224.41,2364.49 1224.41,2334.59 1270.31,2288.69 U2.5@1270.31,2279.53 1270.31,2258.69 1291.78,2237.22 1291.78,2222.25 U2.2@1290,2220.47 1291.91,2218.57 1291.91,2140.52 R4.1@1275,2123.62
DPROUTE: J3.3 R2.1 U2.3 | length 273.4
  Top Layer w8: J3.3@1250,2364.49 1250,2337.6 1288.09,2299.51 1288.09,2263.53 1307.78,2243.85 1307.78,2225.32 1307.91,2225.19 1307.91,2222.25 U2.3@1309.68,2220.47 1307.91,2218.69 1307.91,2212.34 1308,2212.24 1308,2140.62 R2.1@1325,2123.62
GLED: R8.1 U4.9 | length 170.5
  Top Layer w8: R8.1@948.63,1525 980,1525 1001.87,1503.13 1001.87,1423.13 1009.85,1415.15 U4.9@1026.78,1415.15
GLEDA: D2.2 R8.2 | length 129.8
  Top Layer w8: D2.2@800,1456.5 868.5,1525 R8.2@901.38,1525
GND: C1.2 C2.2 C3.2 C5.2 C6.2 C7.2 C8.2 C10.2 C11.2 C12.2 C13.2 C14.2 C15.2 C16.1 C17.1 C18.2 C19.2 C20.2 C21.2 C22.2 C23.2 C25.2 C26.2 C27.2 D1.2 D2.1 D3.1 J2.2 J3.5 J4.4 J5.9 R3.1 R5.1 TP9.1 TP10.1 U1.2 U2.4 U3.2 U4.14 U4.16 U4.39 U4.49 U4.56 U4.65 U5.8 U5.11 U6.2 Y1.2 Y1.4 | length 3085.1
  Top Layer w8: U4.16@1026.78,1277.36 1052.36,1277.36 ; U4.14@1026.78,1316.73 1045.55,1316.73 ; 1347.68,1579.45 U4.49@1347.68,1598.23 1347.68,1615.51 1364.43,1632.26 1364.43,1691.17 1379.12,1705.86 1394.14,1705.86
  Top Layer w10: v1(602,1762) U6.2@602,1803.32 ; U3.2@602,1930.68 v1(602,1972) ; C23.2@890,1196.5 C23.2@893.5,1200 ; 1045.55,1316.73 1091.73,1316.73 ; 1052.36,1277.36 1091.73,1316.73 ; Y1.4@1088.59,1904.72 1088.59,1854.41 1096,1847 v1(1096,1712) ; 1092.15,1317.15 1091.73,1316.73 ; 1092.56,1316.73 1091.73,1316.73 ; U4.65@1125,1350 v2(1126.18,1351.18) v2(1200,1425) ; C14.2@1148.63,2055 1148.63,2035.88 1161.42,2023.08 Y1.2@1161.42,1995.27 ; U5.8@1150,844.88 v2(1150,877.36) U5.11@1150,900 ; 1171.05,1841 1171.13,1841.07 ; 1171.13,1841.13 1171.13,1841.07 ; 1209.85,1532.44 U4.56@1209.85,1598.23 1209.85,1636.01 1171.13,1674.74 1171.13,1841.07 ; v1(1225,1850) 1180.05,1850 1171.13,1841.07 ; 1307.44,1395.47 U4.39@1373.23,1395.47 1444.53,1395.47 1458.62,1381.38 C27.2@1500,1381.38 ; 1325,1550 1347.68,1572.68 1347.68,1579.45 ; R3.1@1375,2123.62 C8.2@1425,2123.62
  Top Layer w12: U2.4@1309.68,2279.53 1309.68,2305.32
  Top Layer w15: v1(713,1634) 819.38,1634 C15.2@820.38,1635 ; v1(767.13,1825) C3.2@818.51,1825 C3.2@825,1831.49 ; v1(775,2050) C2.2@826.38,2050 826.38,2033.62 850,2010 U1.2@850,1987.4 ; v1(800,343) C21.2@800,393.5 ; D3.1@800,1068.5 v1(850.5,1068.5) ; v1(800,1343) D2.1@800,1393.5 ; C25.2@901.38,1375 v1(901.38,1423.62) ; C22.2@950,456.5 v1(950,507) ; C13.2@1225,1971.63 C13.2@1225,1973.62 v1(1225.01,2023.01) ; v1(1298.62,653.62) C10.2@1298.62,700 v1(1345,700) ; v1(1298.62,796.38) C11.2@1298.62,750 v1(1345,750) ; J3.5@1301.18,2364.49 1301.18,2313.82 1309.68,2305.32 ; C17.1@1350,456.5 v1(1350,507) ; R3.1@1375,2123.62 v1(1375,2175) ; C8.2@1425,2124.25 1474.75,2124.25 v1(1475,2124) ; v1(1500,343) C16.1@1500,393.5 ; v1(1500,1335) C27.2@1500,1381.38
  Top Layer w20: v1(784,2475) D1.2@835.54,2475 ; v1(810,2350) C6.2@866.54,2350 ; C1.2@975,1983.5 v1(1026.37,1983.5) ; v1(1025,1065) C19.2@1025,1118.5 ; v1(1125,2125) C7.2@1125,2176.37 ; C18.2@1200,1798.62 1200,1825 v1(1225,1850) 1250,1825 C20.2@1250,1798.62 ; v1(1275.49,931.49) C12.2@1325,931.49 v1(1325,981)
  other v1: 500,50 675,50 1625,50 1800,50 2200,225 75,250 800,275 1000,275 1300,275 1500,275 500,400 675,400 1625,400 1800,400 2200,575 75,600 950,625 1050,625 500,750 675,750 1625,750 775,900 1000,900 2200,925 75,950 500,1100 675,1100 1275,1100 1625,1275 1800,1275 75,1300 500,1425 2200,1575 75,1650 1625,1750 2200,1925 75,2000 1625,2100 1800,2100 1425,2175 1475,2175 1375,2225 1425,2225 1475,2225 1375,2275 1425,2275 1475,2275 2200,2275 75,2350 1625,2450 1800,2450 500,2500 675,2500
  other v2: 1112.6,900 1187.4,900 1150,922.63 1200,1351.18 1273.82,1351.18 1200,1388.09 1126.18,1425 1163.09,1425 1236.91,1425 1273.82,1425 1200,1461.91 1126.18,1498.82 1200,1498.82 1273.82,1498.82
GPIO1: J2.19 U4.30 | length 1117.6
  Top Layer w8: U4.30@1308.3,1251.77 1308.3,1191.7 1870,630 1870,480 J2.19@1950,400
GPIO2: J2.17 U4.31 | length 1009.4
  Top Layer w8: U4.31@1327.99,1251.77 1327.99,1194.46 1885.87,636.58 1885.87,564.13 J2.17@1950,500
GPIO3: J2.15 U4.32 | length 901.3
  Top Layer w8: U4.32@1347.68,1251.77 1347.68,1202.32 J2.15@1950,600
INA: C16.2 R10.1 TP4.1 U5.7 | length 769
  Top Layer w10: U5.7@1130.32,844.88 1130.32,616.68 1172,575 TP4.1@1450,575 1450,520 1425,495 R10.1@1425,456.5 C16.2@1500,456.5
INB: C21.1 R11.1 TP8.1 U5.6 | length 711.2
  Top Layer w10: C21.1@800,456.5 R11.1@875,456.5 875,495 850,520 TP8.1@850,575 1071,575 1110.63,614.63 U5.6@1110.63,844.88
